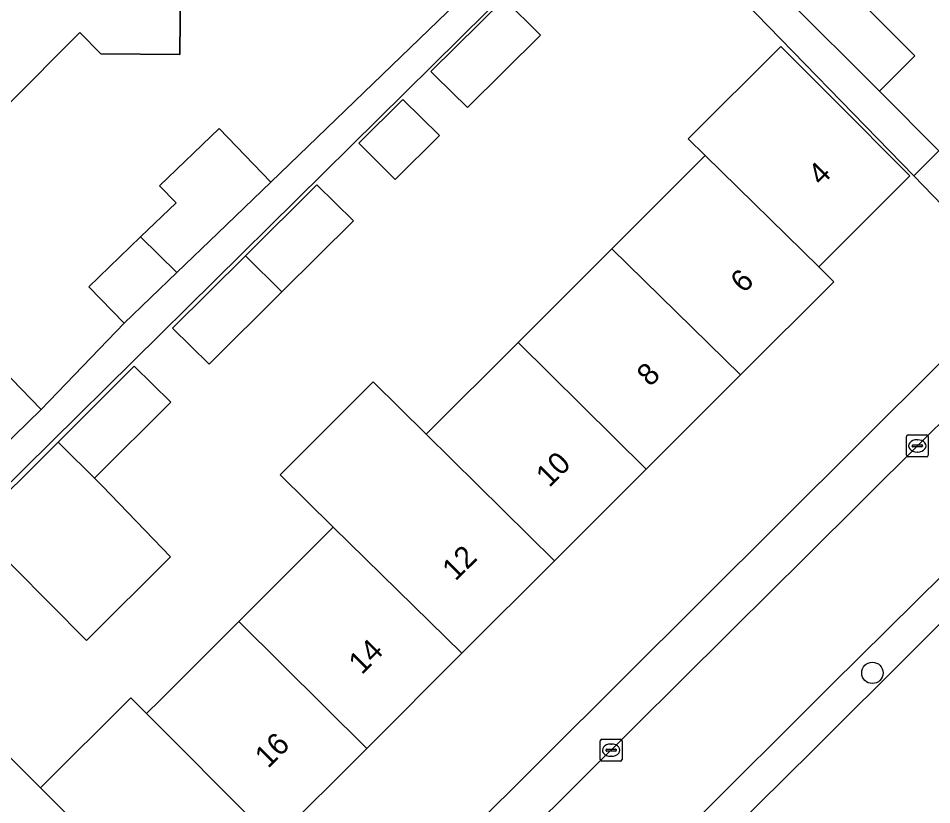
# Model space of a CAD drawing. Extents: x 159960 to 160866, y 382700 to 383354.
# Drawn here: x 160271.97 to 160313.77, y 383105.05 to 383141.06 of the extents above; entities that cross this region are included whole.
import ezdxf

# ---------------------------------------------------------------- set-up
doc = ezdxf.new("R2010")
doc.units = 0
for name, color, linetype in [('IMGEO_Boom', 7, 'Continuous'), ('IMGEO_Erf', 7, 'Continuous'), ('IMGEO_Kolk', 7, 'Continuous'), ('IMGEO_Pand', 7, 'Continuous'), ('IMGEO_Pand_nummerreeks', 7, 'Continuous'), ('IMGEO_Rijbaan_lokaal_gesloten', 7, 'Continuous'), ('IMGEO_Verkeerseiland_open', 7, 'Continuous'), ('IMGEO_Voetpad_open', 7, 'Continuous')]:
    doc.layers.add(name, color=color, linetype=linetype)

msp = doc.modelspace()

# ---------------------------------------------------------------- linework, layer by layer
at = {"layer": 'IMGEO_Boom'}
msp.add_circle((160311.054, 383111.092), 0.489, dxfattribs=at)
at = {"layer": 'IMGEO_Erf'}
for points in [[(160271.204, 383125.023), (160273.019, 383123.141), (160276.812, 383127.095), (160275.198, 383128.768), (160277.564, 383131.048), (160279.184, 383132.609), (160278.435, 383133.386), (160281.158, 383136.01), (160283.519, 383133.562), (160295.852, 383145.458), (160274.571, 383166.453), (160272.87, 383164.782), (160270.751, 383166.941)], [(160271.456, 383151.604), (160275.547, 383147.534), (160275.555, 383144.38), (160279.403, 383144.34), (160279.352, 383139.4), (160275.747, 383139.437), (160274.777, 383140.403), (160271.462, 383137.072)], [(160308.737, 383143.597), (160312.99, 383139.346), (160311.372, 383137.727), (160314.099, 383134.997), (160322.256, 383143.204)], [(160270.774, 383108.032), (160272.986, 383105.828), (160277.11, 383109.949), (160277.832, 383109.225), (160278.467, 383109.86), (160282.056, 383113.446), (160286.382, 383117.768), (160283.949, 383120.158), (160288.206, 383124.411), (160290.633, 383122.016), (160294.843, 383126.222), (160299.13, 383130.506), (160303.338, 383134.71), (160303.402, 383134.774), (160302.626, 383135.533), (160306.859, 383139.763), (160309.238, 383137.381), (160312.773, 383133.844), (160308.606, 383129.681), (160309.285, 383128.991), (160305.023, 383124.732), (160300.708, 383120.421), (160296.504, 383116.221), (160292.265, 383111.986), (160287.91, 383107.635), (160283.659, 383103.387)]]:
    msp.add_lwpolyline(points, dxfattribs=at)
for points in [[(160317.749, 383128.872), (160312.955, 383133.845), (160299.647, 383147.532), (160269.731, 383117.974), (160269.177, 383118.534), (160268.029, 383117.389), (160269.72, 383115.677), (160266.437, 383112.352), (160263.067, 383108.94), (160261.921, 383110.101), (160243.414, 383091.22), (160245.084, 383089.53), (160241.693, 383086.103), (160238.297, 383082.67), (160236.55, 383084.438), (160235.723, 383083.544), (160237.518, 383081.722), (160232.527, 383076.804), (160248.572, 383060.664), (160250.829, 383062.553), (160255.939, 383067.31)], [(160291.045, 383138.429), (160290.847, 383138.623), (160294.196, 383141.954), (160295.859, 383140.289), (160292.528, 383136.976)], [(160287.546, 383135.34), (160289.565, 383137.348), (160291.237, 383135.692), (160289.218, 383133.685)], [(160282.359, 383130.183), (160285.631, 383133.437), (160287.304, 383131.781), (160284.034, 383128.529), (160280.704, 383125.218), (160279.025, 383126.867)], [(160270.092, 383117.609), (160269.905, 383117.798), (160273.786, 383121.657), (160277.274, 383125.126), (160278.953, 383123.477), (160275.456, 383119.999), (160275.806, 383119.652), (160278.927, 383116.397), (160275.082, 383112.566)]]:
    msp.add_lwpolyline(points, close=True, dxfattribs=at)
at = {"layer": 'IMGEO_Kolk'}
for p, q in [((160312.61, 383121.056), (160312.61, 383121.908)), ((160312.685, 383121.982), (160313.537, 383121.982)), ((160313.611, 383121.908), (160313.611, 383121.056)), ((160312.869, 383121.476), (160312.869, 383121.488)), ((160312.912, 383121.525), (160313.31, 383121.525)), ((160313.098, 383121.762), (160313.123, 383121.762)), ((160313.353, 383121.488), (160313.353, 383121.476)), ((160313.307, 383121.439), (160312.909, 383121.439)), ((160313.121, 383121.202), (160313.096, 383121.202)), ((160313.537, 383120.982), (160312.685, 383120.982)), ((160298.597, 383107.127), (160298.597, 383107.979)), ((160298.672, 383108.053), (160299.524, 383108.053)), ((160299.085, 383107.833), (160299.11, 383107.833)), ((160299.598, 383107.979), (160299.598, 383107.127)), ((160298.856, 383107.547), (160298.856, 383107.559)), ((160299.294, 383107.51), (160298.896, 383107.51)), ((160298.899, 383107.596), (160299.297, 383107.596)), ((160299.108, 383107.273), (160299.083, 383107.273)), ((160299.34, 383107.559), (160299.34, 383107.547)), ((160299.524, 383107.053), (160298.672, 383107.053))]:
    msp.add_line(p, q, dxfattribs=at)
for points in [[(160312.61, 383121.056), (160312.61, 383121.908)], [(160312.685, 383121.982), (160313.537, 383121.982)], [(160313.611, 383121.908), (160313.611, 383121.056)], [(160313.537, 383120.982), (160312.685, 383120.982)], [(160298.597, 383107.127), (160298.597, 383107.979)], [(160298.672, 383108.053), (160299.524, 383108.053)], [(160299.598, 383107.979), (160299.598, 383107.127)], [(160299.524, 383107.053), (160298.672, 383107.053)]]:
    msp.add_lwpolyline(points, dxfattribs=at)
for centre, radius, start, end in [((160312.687, 383121.906), 0.0765, 91.552, 178.448), ((160312.687, 383121.906), 0.0765, 91.552, 178.448), ((160313.535, 383121.906), 0.0765, 1.552, 88.448), ((160313.535, 383121.906), 0.0765, 1.552, 88.448), ((160312.909, 383121.485), 0.0403, 85.8775, 175.7526), ((160313.314, 383121.487), 0.0386, 1.7309, 96.639), ((160312.906, 383121.475), 0.0366, 178.938, 274.7102), ((160313.31, 383121.482), 0.043, 264.8664, 352.4533), ((160312.687, 383121.058), 0.0765, 181.552, 268.448), ((160312.687, 383121.058), 0.0765, 181.552, 268.448), ((160313.535, 383121.058), 0.0765, 271.552, 358.448), ((160313.535, 383121.058), 0.0765, 271.552, 358.448), ((160298.674, 383107.977), 0.0765, 91.552, 178.448), ((160298.674, 383107.977), 0.0765, 91.552, 178.448), ((160299.522, 383107.977), 0.0765, 1.552, 88.448), ((160299.522, 383107.977), 0.0765, 1.552, 88.448), ((160298.896, 383107.556), 0.0403, 85.8775, 175.7526), ((160298.893, 383107.546), 0.0366, 178.938, 274.7102), ((160299.297, 383107.553), 0.043, 264.8664, 352.4533), ((160299.301, 383107.558), 0.0386, 1.7309, 96.639), ((160298.674, 383107.129), 0.0765, 181.552, 268.448), ((160298.674, 383107.129), 0.0765, 181.552, 268.448), ((160299.522, 383107.129), 0.0765, 271.552, 358.448), ((160299.522, 383107.129), 0.0765, 271.552, 358.448)]:
    msp.add_arc(centre, radius, start, end, dxfattribs=at)
for centre, major_axis, ratio, start_param, end_param in [((160313.097, 383121.482), (-0.387, 0.002), 0.722429, 4.712389, 7.853982), ((160313.122, 383121.482), (-0.39, 0.002), 0.717154, 1.570796, 4.712389), ((160299.084, 383107.553), (-0.387, 0.002), 0.722429, 4.712389, 7.853982), ((160299.109, 383107.553), (-0.39, 0.002), 0.717154, 1.570796, 4.712389)]:
    msp.add_ellipse(centre, major_axis=major_axis, ratio=ratio, start_param=start_param, end_param=end_param, dxfattribs=at)
at = {"layer": 'IMGEO_Pand'}
for points in [[(160275.555, 383144.38), (160275.555, 383144.319), (160267.477, 383144.144), (160267.301, 383144.322), (160265.761, 383142.775), (160271.462, 383137.072), (160274.777, 383140.403), (160275.747, 383139.437), (160279.352, 383139.4), (160279.403, 383144.34)], [(160311.372, 383137.727), (160312.99, 383139.346), (160308.737, 383143.597), (160307.119, 383141.978)], [(160291.045, 383138.429), (160292.528, 383136.976), (160295.859, 383140.289), (160294.196, 383141.954), (160290.847, 383138.623)], [(160309.238, 383137.381), (160306.859, 383139.763), (160302.626, 383135.533), (160303.402, 383134.774), (160308.606, 383129.681), (160312.773, 383133.844)], [(160287.546, 383135.34), (160289.218, 383133.685), (160291.237, 383135.692), (160289.565, 383137.348)], [(160283.519, 383133.562), (160281.158, 383136.01), (160278.435, 383133.386), (160279.184, 383132.609), (160277.564, 383131.048), (160279.219, 383129.415), (160281.095, 383131.224)], [(160303.402, 383134.774), (160303.338, 383134.71), (160299.13, 383130.506), (160305.023, 383124.732), (160309.285, 383128.991), (160308.606, 383129.681)], [(160282.359, 383130.183), (160284.034, 383128.529), (160287.304, 383131.781), (160285.631, 383133.437)], [(160279.219, 383129.415), (160277.564, 383131.048), (160275.198, 383128.768), (160276.812, 383127.095)], [(160299.13, 383130.506), (160294.843, 383126.222), (160300.708, 383120.421), (160305.023, 383124.732)], [(160284.034, 383128.529), (160282.359, 383130.183), (160279.025, 383126.867), (160280.704, 383125.218)], [(160296.504, 383116.221), (160300.708, 383120.421), (160294.843, 383126.222), (160290.633, 383122.016)], [(160269.296, 383123.183), (160270.896, 383121.59), (160271.148, 383121.338), (160273.019, 383123.141), (160271.204, 383125.023)], [(160273.786, 383121.657), (160273.984, 383121.461), (160275.456, 383119.999), (160278.953, 383123.477), (160277.274, 383125.126)], [(160296.504, 383116.221), (160290.633, 383122.016), (160288.206, 383124.411), (160283.949, 383120.158), (160286.382, 383117.768), (160292.265, 383111.986)], [(160275.806, 383119.652), (160275.456, 383119.999), (160273.984, 383121.461), (160273.786, 383121.657), (160269.905, 383117.798), (160270.092, 383117.609), (160275.082, 383112.566), (160278.927, 383116.397)], [(160282.056, 383113.446), (160287.91, 383107.635), (160292.265, 383111.986), (160286.382, 383117.768)], [(160282.056, 383113.446), (160278.467, 383109.86), (160277.832, 383109.225), (160282.965, 383104.083), (160283.659, 383103.387), (160287.91, 383107.635)], [(160277.832, 383109.225), (160277.11, 383109.949), (160272.986, 383105.828), (160278.857, 383099.979), (160282.861, 383103.979), (160282.965, 383104.083)], [(160278.857, 383099.979), (160272.986, 383105.828), (160270.774, 383108.032), (160270.565, 383107.823), (160266.433, 383103.695), (160268.651, 383101.497), (160269.35, 383100.804), (160274.537, 383095.662), (160274.621, 383095.746)]]:
    msp.add_lwpolyline(points, close=True, dxfattribs=at)
at = {"layer": 'IMGEO_Rijbaan_lokaal_gesloten'}
for points in [[(160335.75, 383144.078), (160334.774, 383142.62), (160332.911, 383143.971), (160328.441, 383138.034), (160326.653, 383135.616), (160324.944, 383133.756), (160322.392, 383130.859), (160319.117, 383127.466), (160318.817, 383127.156), (160317.426, 383125.773), (160314.713, 383123.076), (160313.267, 383121.64), (160307.97, 383116.373), (160304.709, 383113.133), (160302.054, 383110.493), (160300.398, 383108.847), (160295.024, 383103.505), (160291.852, 383100.352), (160286.471, 383094.979), (160283.542, 383092.054), (160280.881, 383089.396), (160279.133, 383087.652), (160273.778, 383082.303), (160270.531, 383079.062)], [(160326.53, 383125.733), (160323.63, 383122.827), (160317.799, 383116.986), (160308.34, 383107.547), (160303.301, 383102.567), (160299.87, 383099.011), (160287.105, 383086.228), (160269.578, 383068.725), (160257.319, 383056.597), (160262.97, 383050.94), (160286.618, 383074.417), (160308.497, 383096.209), (160311.713, 383099.5), (160329.197, 383117.105)], [(160285.724, 383087.065), (160294.588, 383095.902), (160298.008, 383099.331), (160302.578, 383103.945), (160309.183, 383110.548), (160315.589, 383116.881), (160322.474, 383123.785)]]:
    msp.add_lwpolyline(points, dxfattribs=at)
at = {"layer": 'IMGEO_Verkeerseiland_open'}
for points in [[(160322.474, 383123.785), (160315.589, 383116.881), (160309.183, 383110.548), (160302.578, 383103.945), (160298.008, 383099.331), (160294.588, 383095.902), (160285.724, 383087.065), (160275.283, 383076.626), (160264.932, 383066.316), (160260.81, 383062.259), (160259.545, 383060.959), (160258.244, 383059.694), (160256.492, 383058.098), (160254.7, 383056.547), (160253.564, 383055.617), (160252.423, 383054.693), (160251.322, 383053.759), (160250.217, 383052.829), (160250, 383052.657), (160248.809, 383051.683), (160247.59, 383050.744), (160246.666, 383050.082)], [(160229.941, 383030.558), (160230.481, 383031.072), (160237.264, 383037.374), (160239.281, 383039.309), (160253.577, 383052.895), (160257.319, 383056.597), (160269.578, 383068.725), (160287.105, 383086.228), (160299.87, 383099.011), (160303.301, 383102.567), (160308.34, 383107.547), (160317.799, 383116.986)]]:
    msp.add_lwpolyline(points, dxfattribs=at)
at = {"layer": 'IMGEO_Voetpad_open'}
for points in [[(160269.731, 383117.974), (160299.647, 383147.532), (160312.955, 383133.845), (160314.099, 383134.997), (160311.372, 383137.727), (160307.119, 383141.978), (160303.951, 383144.952), (160301.117, 383147.793), (160299.029, 383149.854), (160297.796, 383151.092), (160297.221, 383151.669), (160294.189, 383148.677), (160289.986, 383152.936), (160287.364, 383155.593), (160285.234, 383157.752), (160283.977, 383159.026), (160282.69, 383160.33), (160280.6, 383162.448), (160279.117, 383163.951), (160276.466, 383166.613), (160273.917, 383169.253), (160272.408, 383170.816), (160269.673, 383173.403)], [(160268.949, 383172.18), (160272.434, 383168.63), (160274.571, 383166.453), (160295.852, 383145.458), (160283.519, 383133.562), (160281.095, 383131.224), (160279.219, 383129.415), (160276.812, 383127.095), (160273.019, 383123.141), (160271.148, 383121.338)], [(160337.405, 383155.839), (160336.194, 383157.057), (160333.148, 383153.955), (160322.256, 383143.204), (160314.099, 383134.997), (160312.955, 383133.845), (160317.749, 383128.872), (160255.939, 383067.31), (160250.829, 383062.553), (160248.572, 383060.664), (160247.485, 383059.754), (160244.046, 383056.876)], [(160270.531, 383079.062), (160273.778, 383082.303), (160279.133, 383087.652), (160280.881, 383089.396), (160283.542, 383092.054), (160286.471, 383094.979), (160291.852, 383100.352), (160295.024, 383103.505), (160300.398, 383108.847), (160302.054, 383110.493), (160304.709, 383113.133), (160307.97, 383116.373), (160313.267, 383121.64), (160314.713, 383123.076), (160317.426, 383125.773), (160318.817, 383127.156), (160319.117, 383127.466), (160322.392, 383130.859), (160324.944, 383133.756), (160326.653, 383135.616), (160328.441, 383138.034), (160332.911, 383143.971), (160337.678, 383151.279)]]:
    msp.add_lwpolyline(points, dxfattribs=at)

# ---------------------------------------------------------------- texts
at = {"layer": 'IMGEO_Pand_nummerreeks'}
for s, rotation, p in [('4', 44.9715, (160308.711, 383133.349)), ('6', 44.9772, (160305.165, 383128.437)), ('8', 44.9744, (160300.88, 383124.155)), ('10', 44.9744, (160296.264, 383119.545)), ('12', 44.9744, (160291.972, 383115.257)), ('14', 44.9744, (160287.686, 383110.974)), ('16', 44.9772, (160283.397, 383106.689))]:
    msp.add_text(s, height=1, rotation=rotation, dxfattribs=at).set_placement(p)

doc.saveas('drawing.dxf')
